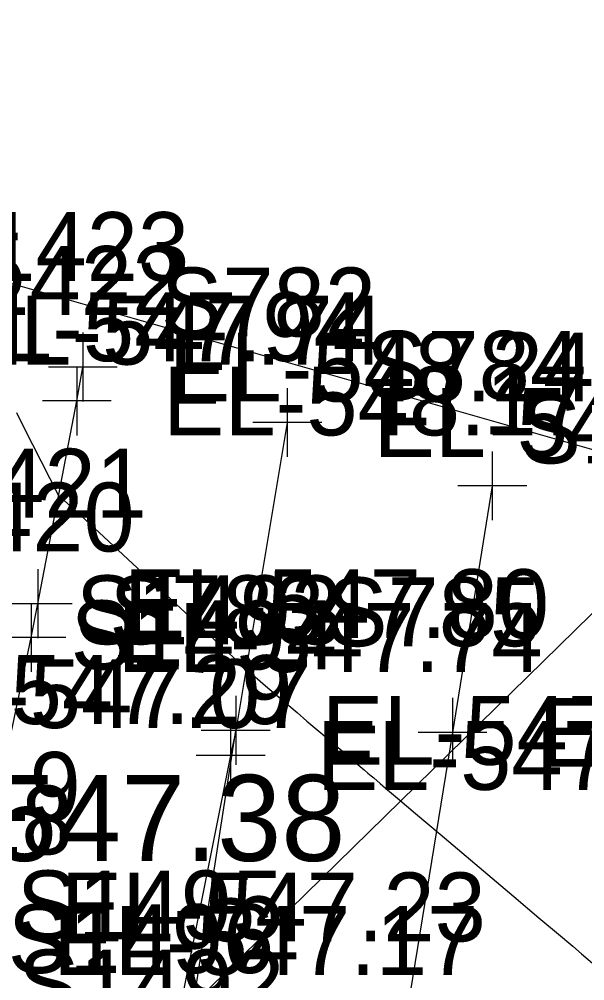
# Model space of a CAD drawing. Extents: x 1724534 to 1727318, y 657156 to 660047.
# Drawn here: x 1725649.6 to 1725682.4, y 659767.6 to 659823.4 of the extents above; entities that cross this region are included whole.
import ezdxf

# ---------------------------------------------------------------- set-up
doc = ezdxf.new("R2010")
doc.units = 0
for name, color, linetype in [('SURVEY - CENTERLINE - Preliminary Text', 7, 'Continuous'), ('SURVEY - CONTOURS - Intermediate with optional Text', 7, 'Continuous'), ('SURVEY - CONTROL - Points - Elevations', 7, 'Continuous'), ('SURVEY - DRAINAGE - Area Shapes', 7, 'Continuous'), ('SURVEY - DTM - Breaklines - Points - Elevations', 7, 'Continuous'), ('SURVEY - NON-TRANSPORTATION - Features - Points - Elevations', 7, 'Continuous'), ('SURVEY - TRAFFIC CONTROL - Pavement Marking - Points - Elevations', 7, 'Continuous'), ('SURVEY - TRAFFIC CONTROL - Pavement Marking - Points - Locators', 7, 'Continuous'), ('SURVEY - TRAFFIC CONTROL - Pavement Marking - Points - Numbers', 7, 'Continuous'), ('SURVEY - TRAFFIC CONTROL - Pavement Marking with Text', 7, 'Continuous'), ('SURVEY - TRANSPORTATION - Features - Points - Elevations', 7, 'Continuous'), ('SURVEY - TRANSPORTATION - Roads', 7, 'Continuous'), ('SURVEY - TRANSPORTATION - Roads - Points - Elevations', 7, 'Continuous'), ('SURVEY - TRANSPORTATION - Roads - Points - Locators', 7, 'Continuous'), ('SURVEY - TRANSPORTATION - Roads - Points - Numbers', 7, 'Continuous')]:
    doc.layers.add(name, color=color, linetype=linetype)

msp = doc.modelspace()

# ---------------------------------------------------------------- linework, layer by layer
at = {"layer": 'SURVEY - CENTERLINE - Preliminary Text'}
msp.add_line((1725658.702, 659765.224), (1725703.392, 659809.008), dxfattribs=at)
at = {"layer": 'SURVEY - CONTOURS - Intermediate with optional Text'}
msp.add_lwpolyline([(1725649.45, 659800.56), (1725649.888, 659799.698), (1725651.9, 659795.746), (1725652.576, 659795.137), (1725652.889, 659794.85), (1725654.521, 659793.335), (1725659.804, 659788.418), (1725661.184, 659787.14), (1725662.351, 659786.072), (1725663.305, 659785.217), (1725664.047, 659784.572), (1725665.739, 659783.134), (1725666.317, 659782.644), (1725666.78, 659782.249), (1725667.13, 659781.952), (1725667.366, 659781.751), (1725667.844, 659781.343), (1725668.033, 659781.182), (1725668.241, 659781.004), (1725668.469, 659780.809), (1725668.717, 659780.597), (1725669.403, 659780.011), (1725669.646, 659779.804), (1725669.859, 659779.623), (1725670.041, 659779.467), (1725670.194, 659779.336), (1725670.561, 659779.023), (1725670.882, 659778.75), (1725671.571, 659778.167), (1725672.626, 659777.273), (1725674.048, 659776.07), (1725678.331, 659772.447), (1725679.781, 659771.22), (1725680.918, 659770.256), (1725681.743, 659769.557), (1725682.257, 659769.121), (1725683.922, 659767.702)], dxfattribs=at)
at = {"layer": 'SURVEY - DRAINAGE - Area Shapes'}
msp.add_lwpolyline([(1725496.032, 659791.425), (1725595.449, 659823.409), (1725690.966, 659796.106), (1725676.22, 659724.326), (1725483.401, 659755.229)], close=True, dxfattribs=at)
at = {"layer": 'SURVEY - TRAFFIC CONTROL - Pavement Marking - Points - Locators'}
for p, q in [((1725665.173, 659801.983), (1725665.173, 659797.983)), ((1725667.173, 659799.983), (1725663.173, 659799.983)), ((1725677.077, 659798.306), (1725677.077, 659794.306)), ((1725679.077, 659796.306), (1725675.077, 659796.306)), ((1725662.184, 659784.1), (1725662.184, 659780.1)), ((1725674.763, 659783.986), (1725674.763, 659779.986)), ((1725664.184, 659782.1), (1725660.184, 659782.1)), ((1725676.763, 659781.986), (1725672.763, 659781.986))]:
    msp.add_line(p, q, dxfattribs=at)
at = {"layer": 'SURVEY - TRAFFIC CONTROL - Pavement Marking with Text'}
msp.add_line((1725665.173, 659799.983), (1725662.184, 659782.1), dxfattribs=at)
msp.add_lwpolyline([(1725677.077, 659796.306), (1725674.763, 659781.986), (1725662.242, 659705.025), (1725649.129, 659624.102), (1725636.683, 659547.114), (1725636.368, 659545.139), (1725624.177, 659468.103), (1725623.248, 659462.175), (1725617.375, 659424.632), (1725617.069, 659422.656), (1725605.507, 659345.515), (1725605.215, 659343.536), (1725602.951, 659328.104)], dxfattribs=at)
at = {"layer": 'SURVEY - TRANSPORTATION - Roads'}
for points in [[(1725603.37, 659597.283), (1725609.346, 659620.521), (1725610.838, 659626.331), (1725616.118, 659647.682), (1725616.609, 659649.621), (1725622.545, 659672.869), (1725623.043, 659674.805), (1725627.074, 659690.284), (1725627.572, 659692.221), (1725631.909, 659709.685), (1725632.405, 659711.621), (1725638.875, 659736.793), (1725639.344, 659738.736), (1725642.879, 659754.334), (1725646.579, 659769.894), (1725647.02, 659771.844), (1725650.31, 659787.495), (1725650.689, 659789.457), (1725652.957, 659801.236), (1725653.303, 659803.205)], [(1725658.822, 659760.366), (1725662.184, 659782.1), (1725661.882, 659780.645), (1725658.752, 659764.961)]]:
    msp.add_lwpolyline(points, dxfattribs=at)
at = {"layer": 'SURVEY - TRANSPORTATION - Roads - Points - Locators'}
for p, q in [((1725653.303, 659805.205), (1725653.303, 659801.205)), ((1725655.303, 659803.205), (1725651.303, 659803.205)), ((1725652.957, 659803.236), (1725652.957, 659799.236)), ((1725654.957, 659801.236), (1725650.957, 659801.236)), ((1725650.689, 659791.457), (1725650.689, 659787.457)), ((1725652.689, 659789.457), (1725648.689, 659789.457)), ((1725650.31, 659789.495), (1725650.31, 659785.495)), ((1725652.31, 659787.495), (1725648.31, 659787.495)), ((1725662.184, 659784.1), (1725662.184, 659780.1)), ((1725661.882, 659782.645), (1725661.882, 659778.645)), ((1725664.184, 659782.1), (1725660.184, 659782.1)), ((1725663.882, 659780.645), (1725659.882, 659780.645))]:
    msp.add_line(p, q, dxfattribs=at)

# ---------------------------------------------------------------- texts
at = {"layer": 'SURVEY - CONTROL - Points - Elevations'}
msp.add_text('EL-547.38', height=5, dxfattribs=at).set_placement((1725637.689, 659774.516))
at = {"layer": 'SURVEY - DTM - Breaklines - Points - Elevations'}
for s, p in [('EL-547.94', (1725644.982, 659803.546)), ('EL-547.29', (1725640.79, 659782.47))]:
    msp.add_text(s, height=4, dxfattribs=at).set_placement(p)
at = {"layer": 'SURVEY - NON-TRANSPORTATION - Features - Points - Elevations'}
msp.add_text('EL-552.65', height=4, dxfattribs=at).set_placement((1725625.281, 659807.007))
at = {"layer": 'SURVEY - TRAFFIC CONTROL - Pavement Marking - Points - Elevations'}
for s, p in [('EL-548.43', (1725670.173, 659797.983)), ('EL-547.89', (1725667.184, 659780.1)), ('EL-548.17', (1725679.763, 659779.986))]:
    msp.add_text(s, height=4, dxfattribs=at).set_placement(p)
at = {"layer": 'SURVEY - TRAFFIC CONTROL - Pavement Marking - Points - Numbers'}
for s, p in [('S782', (1725657.837, 659804.983)), ('S784', (1725669.741, 659801.306)), ('S783', (1725654.848, 659787.1)), ('S785', (1725667.427, 659786.986))]:
    msp.add_text(s, height=4, dxfattribs=at).set_placement(p)
at = {"layer": 'SURVEY - TRANSPORTATION - Features - Points - Elevations'}
for s, p in [('EL-547.74', (1725646.101, 659803.349)), ('EL-547.07', (1725641.902, 659782.236))]:
    msp.add_text(s, height=4, dxfattribs=at).set_placement(p)
at = {"layer": 'SURVEY - TRANSPORTATION - Roads - Points - Elevations'}
for s, p in [('EL-548.24', (1725658.303, 659801.205)), ('EL-548.17', (1725657.957, 659799.236)), ('EL-547.80', (1725655.689, 659787.457)), ('EL-547.74', (1725655.31, 659785.495)), ('EL-547.89', (1725667.184, 659780.1)), ('EL-547.87', (1725666.882, 659778.645)), ('EL-547.23', (1725652.02, 659769.844)), ('EL-547.17', (1725651.579, 659767.894))]:
    msp.add_text(s, height=4, dxfattribs=at).set_placement(p)
at = {"layer": 'SURVEY - TRANSPORTATION - Roads - Points - Numbers'}
for s, p in [('S1423', (1725644.015, 659808.205)), ('S1422', (1725643.669, 659806.236)), ('S1255', (1725678.659, 659797.609)), ('S1421', (1725641.559, 659794.457)), ('S1420', (1725640.849, 659792.495)), ('S1493', (1725652.896, 659787.1)), ('S1494', (1725652.594, 659785.645)), ('S1419', (1725637.717, 659776.844)), ('S1418', (1725637.244, 659774.894)), ('S1495', (1725649.464, 659769.961)), ('S1496', (1725648.948, 659768.003)), ('S1492', (1725649.534, 659765.366))]:
    msp.add_text(s, height=4, dxfattribs=at).set_placement(p)

doc.saveas('drawing.dxf')
